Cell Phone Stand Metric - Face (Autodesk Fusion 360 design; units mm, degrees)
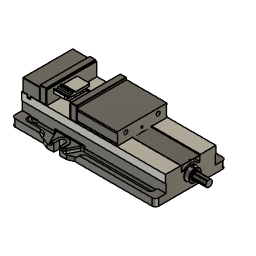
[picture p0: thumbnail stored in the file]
description: HaasClamp
derived_base_feature "Derived Base Feature" bodies "Stand Body"
align "Align1"
base_feature "Base Feature1"
base_feature "Base Feature1"
base_feature "Base Feature1"
base_feature "Base Feature1"
base_feature "Base Feature1"
base_feature "Base Feature1"
base_feature "Base Feature1"
base_feature "Base Feature1"
base_feature "Base Feature1"
base_feature "Base Feature1"
as_built_joint "As-built1"
as_built_joint "As-built2"
as_built_joint "As-built3"
joint_origin "JointOrigin1" OffsetX 0 OffsetY 0 OffsetZ 0 AngleZ 0
joint "Assemble1" alignAngle 180 alignOffsetX 0 alignOffsetY 0 alignOffsetZ 0 (= "jaw_width_haas_050002") SlideMaximum 22.5 SlideMinimum 0
position "Position1"
sketch "Sketch1" plane through (0, -72.5, 0) normal (0, -1, 0) x axis (1, 0, 0)
  line L1 (75, 73) -> (-75, 73)
  line L2 (76, 74) -> (75, 73)
  line L3 (76, 116.5) -> (76, 74)
  line L4 (75, 117.5) -> (76, 116.5)
  line L5 (-75, 117.5) -> (75, 117.5)
  line L6 (-76, 116.5) -> (-75, 117.5)
  line L7 (-76, 74) -> (-76, 116.5)
  line L8 (-75, 73) -> (-76, 74)
  line L9 (76.4, 114.275) -> (-76, 114.275)
  line L10 (76.4, 73) -> (76.4, 114.275)
  line L11 (-76, 73) -> (76.4, 73)
  line L12 (-76, 114.275) -> (-76, 73)
  circle C1 centre (49.21, 96.8) radius 11
  circle C2 centre (-49.21, 96.8) radius 11
  point P14 (76.4, 73)
  point P12 (-76, 114.275)
  point P13 (76.4, 114.275)
  horizontal L9
  vertical L10
  horizontal L11
  vertical L12
  coincident L1 P14
  coincident L7 P12
  dimension "d16" distance P12 P13 = 152.4
  dimension "d17" distance P13 P14 = 41.275
place_component sketch "Sketch1"
extrude "Extrude1" new body sketch "Sketch1" profile of L1 L2 L3 L7 L8 C1 C2 L9 L11 L12 along normal blind 3.175
place_component sketch "Sketch1"
extrude "Extrude1" sketch "Sketch1" profile of L1 L2 L3 L7 L8 C1 C2 L9 L11 L12 blind -3.175
as_built_joint "As-built5"
as_built_joint "As-built6"
sketch "Sketch1" plane through (0, 0, 0) normal (0, 0, -1) x axis (1, 0, 0)
  line L1 (16.5, -37.5) -> (-16.5, -37.5)
  line L2 (20, 34) -> (20, -34)
  line L3 (-16.5, 37.5) -> (16.5, 37.5)
  line L4 (-20, -34) -> (-20, 34)
  line L5 (-38.1, -40) -> (38.1, -40)
  line L6 (-38.1, 40) -> (-38.1, -40)
  line L7 (38.1, 40) -> (-38.1, 40)
  line L8 (38.1, -40) -> (38.1, 40)
  line L9 (-38.1, 40) -> (38.1, -40)
  line L10 (38.1, 40) -> (-38.1, -40)
  arc A1 centre (-16.5, -34) radius 3.5 clockwise from (-16.5, -37.5) to (-20, -34)
  arc A2 centre (16.5, -34) radius 3.5 clockwise from (20, -34) to (16.5, -37.5)
  arc A3 centre (16.5, 34) radius 3.5 clockwise from (16.5, 37.5) to (20, 34)
  arc A4 centre (-16.5, 34) radius 3.5 clockwise from (-20, 34) to (-16.5, 37.5)
  point P18 (0, 0)
  point P1 (0, 0)
  point P16 (-38.1, 40)
  point P17 (38.1, 40)
  point P15 (-38.1, -40)
  horizontal L5
  perpendicular L5 L6
  parallel L5 L7
  parallel L6 L8
  coincident L9 P18
  coincident L10 P18
  coincident P1 P18
  dimension "d1" distance P16 P17 = 76.2
  dimension "d2" distance P15 P16 = 80
extrude "Extrude1" new body sketch "Sketch1" profile of A1 L1 A2 L2 A3 L3 A4 L4 L5 L6 L7 L8 against normal blind 10 bodies "Stock"
position "Position1"
ground "Pin"
position "Position2"
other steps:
create_component "CreateComponent1"
create_component "CreateComponent2"
create_component "CreateComponent3"
create_component "CreateComponent4"
create_component "CreateComponent5"
create_component "CreateComponent6"
create_component "CreateComponent7"
create_component "CreateComponent8"
create_component "CreateComponent9"
create_component "CreateComponent10"
joint_origin "JointOrigin10"
joint_origin "JointOrigin11"
create_component "CreateComponent11" sketch "Sketch1"
create_component "CreateComponent12" sketch "Sketch1"
create_component "CreateComponent1"
named bodies: "Stand Body", "Stock"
